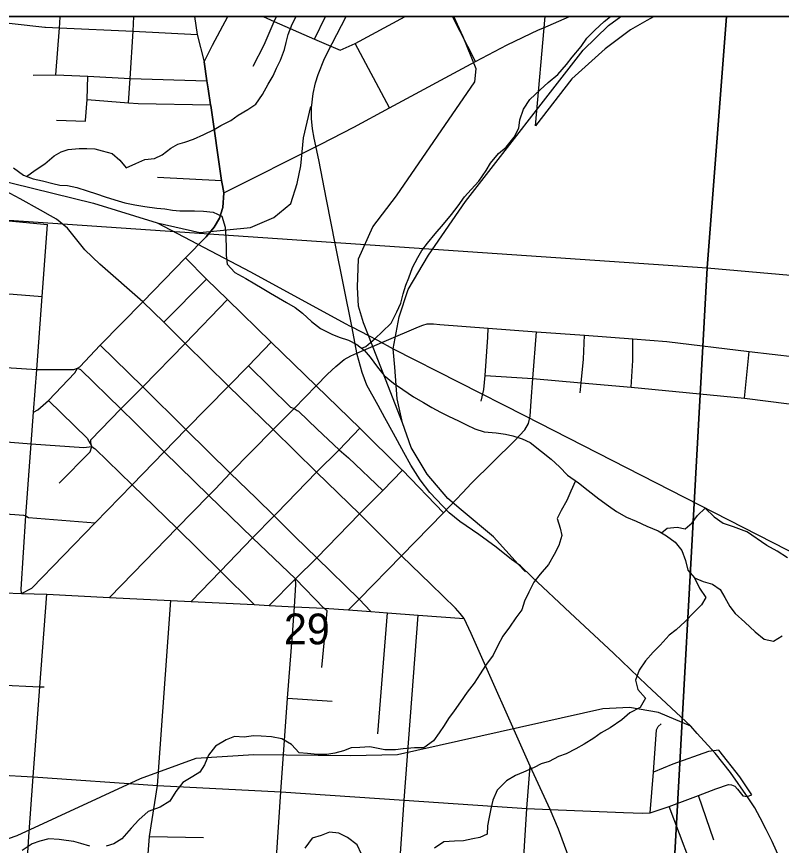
# Model space of a CAD drawing. Extents: x 0 to 42, y 0 to 22.
# Drawn here: x 2.931 to 3.451, y 20.336 to 20.9 of the extents above; entities that cross this region are included whole.
import ezdxf

# ---------------------------------------------------------------- set-up
doc = ezdxf.new("R2010")
doc.units = 0
for name, color, linetype in [('GM_X_City_Street', 7, 'Continuous'), ('GM_X_County_Road', 7, 'Continuous'), ('GM_X_Major_River', 7, 'Continuous'), ('GM_X_Minor_River', 7, 'Continuous'), ('GM_X_Rail_Line', 7, 'Continuous'), ('GM_X_Section', 7, 'Continuous'), ('GM_X_Section_Text', 7, 'Continuous'), ('GM_X_State_Route', 7, 'Continuous'), ('GM_X_Township_Road', 7, 'Continuous'), ('GM_X_Unincorporated', 7, 'Continuous'), ('SH_Cut_Line', 7, 'Continuous'), ('SH_Data', 7, 'Continuous')]:
    doc.layers.add(name, color=color, linetype=linetype)

msp = doc.modelspace()

# ---------------------------------------------------------------- linework, layer by layer
at = {"layer": 'GM_X_City_Street'}
for p, q in [((3.13371, 20.88467), (3.14117, 20.9)), ((3.24329, 20.8695), (3.22767, 20.9)), ((3.18471, 20.83794), (3.16148, 20.88163)), ((3.02687, 20.79076), (3.07048, 20.78857)), ((3.03111, 20.69207), (3.06023, 20.72129)), ((3.42632, 20.64032), (3.42946, 20.67221)), ((3.17687, 20.41197), (3.18328, 20.49428)), ((3.11541, 20.43617), (3.14566, 20.43425)), ((3.40557, 20.33954), (3.39508, 20.37005)), ((3.38911, 20.32526), (3.37516, 20.36249)), ((3.0215, 20.34215), (3.05817, 20.3414))]:
    msp.add_line(p, q, dxfattribs=at)
for points in [[(2.95757, 20.86044), (2.96009, 20.89239), (2.96034, 20.89552), (2.96069, 20.9)], [(3.00714, 20.8414), (3.00818, 20.85794), (3.01021, 20.88997), (3.01084, 20.9)], [(3.092, 20.86632), (3.09944, 20.88087), (3.10628, 20.89667), (3.10779, 20.9)], [(3.0987, 20.9), (3.10628, 20.89667), (3.13371, 20.88467), (3.15126, 20.87715)], [(3.15126, 20.87715), (3.16148, 20.88163), (3.19549, 20.9)], [(2.94219, 20.86006), (2.95757, 20.86044), (2.97944, 20.85935), (3.00818, 20.85794), (3.06047, 20.85628)], [(2.95814, 20.82944), (2.97788, 20.82886), (2.97792, 20.82935), (2.97902, 20.84354), (2.97944, 20.85935)], [(2.97902, 20.84354), (3.00714, 20.8414), (3.01363, 20.84091), (3.063, 20.83988)], [(3.01688, 20.70597), (2.98757, 20.73149), (2.97744, 20.74126), (2.96557, 20.75607), (2.95813, 20.76226), (2.95408, 20.76452), (2.9472, 20.76831), (2.93332, 20.7759), (2.92663, 20.77956), (2.9195, 20.78333), (2.91132, 20.78678), (2.90177, 20.78986), (2.89715, 20.79119), (2.89111, 20.7929), (2.8733, 20.79756), (2.85625, 20.80134)], [(2.81704, 20.76971), (2.85274, 20.76708), (2.88832, 20.76415), (2.92095, 20.76153), (2.95205, 20.75864)], [(2.93423, 20.50754), (2.9341, 20.5105), (2.93735, 20.56038), (2.94095, 20.60938), (2.94243, 20.63084), (2.94472, 20.65997), (2.9484, 20.70964), (2.95205, 20.75864)], [(2.83499, 20.71803), (2.84884, 20.71697), (2.85584, 20.71648), (2.88469, 20.71426), (2.91698, 20.71204), (2.9484, 20.70964)], [(2.95995, 20.58244), (2.98097, 20.60395), (2.98225, 20.60745), (2.98146, 20.61012), (2.98144, 20.61201), (3.00194, 20.63301), (3.01684, 20.64801), (3.0457, 20.67761), (3.07442, 20.70742)], [(3.24713, 20.63831), (3.24888, 20.64634), (3.2499, 20.6557), (3.25178, 20.68195), (3.25196, 20.68801)], [(3.3146, 20.64405), (3.31527, 20.65069), (3.31671, 20.66696), (3.31738, 20.68331)], [(3.34933, 20.64791), (3.3503, 20.666), (3.35034, 20.68066)], [(2.94243, 20.63084), (2.94549, 20.63247), (2.95265, 20.63883), (2.97066, 20.65752), (2.97231, 20.66069)], [(2.97231, 20.66069), (2.97448, 20.65993), (3.00194, 20.63301), (3.01156, 20.62369), (3.03141, 20.60393), (3.06189, 20.5741), (3.09149, 20.54532), (3.12072, 20.51736), (3.13995, 20.49752)], [(3.08877, 20.66235), (3.11739, 20.63424), (3.11982, 20.63325), (3.12192, 20.63198)], [(3.2499, 20.6557), (3.28241, 20.65376), (3.31527, 20.65069), (3.34933, 20.64791), (3.42632, 20.64032), (3.45677, 20.6366), (3.48794, 20.63254), (3.51876, 20.62922)], [(2.95265, 20.63883), (2.9789, 20.61313), (2.98225, 20.60745)], [(3.12192, 20.63198), (3.12275, 20.63147), (3.13554, 20.61929), (3.15055, 20.60518), (3.15694, 20.59987), (3.18027, 20.57751)], [(3.13512, 20.5901), (3.15055, 20.60518), (3.16445, 20.61986)], [(3.10295, 20.49931), (3.12072, 20.51736), (3.13522, 20.53183), (3.16438, 20.56158), (3.18027, 20.57751), (3.19354, 20.59136)], [(3.00954, 20.58149), (3.03994, 20.55188), (3.0697, 20.52264), (3.09259, 20.4999)], [(2.75236, 20.573), (2.80215, 20.5694), (2.8377, 20.5665), (2.87135, 20.56434), (2.87339, 20.56518), (2.89498, 20.56392), (2.90593, 20.56326), (2.9085, 20.56281), (2.93566, 20.56086), (2.93735, 20.56038)], [(2.93735, 20.56038), (2.93912, 20.55926), (2.98444, 20.55561)], [(3.04971, 20.50202), (3.0697, 20.52264), (3.09149, 20.54532), (3.10631, 20.56039)], [(3.17213, 20.49526), (3.16413, 20.5036), (3.13522, 20.53183), (3.12066, 20.54604), (3.10631, 20.56039)], [(3.15693, 20.49625), (3.16413, 20.5036), (3.19295, 20.53306)], [(3.1028, 20.21283), (3.10322, 20.22293), (3.10391, 20.26556), (3.10485, 20.28322), (3.11071, 20.37253), (3.11541, 20.43617), (3.1187, 20.47953), (3.12012, 20.49837), (3.12101, 20.51357), (3.12072, 20.51736)], [(3.01434, 20.25017), (3.0215, 20.34215), (3.02687, 20.37691), (3.03595, 20.50271)], [(3.13873, 20.45716), (3.14042, 20.47591), (3.14235, 20.49557), (3.13995, 20.49752)], [(3.1849, 20.20535), (3.18545, 20.21888), (3.18843, 20.2689), (3.18939, 20.28375), (3.19064, 20.30744), (3.19473, 20.36689), (3.20425, 20.4927)], [(2.88779, 20.44684), (2.91821, 20.44522), (2.94683, 20.44404), (2.94979, 20.44404)], [(3.36217, 20.35834), (3.36431, 20.38587), (3.36635, 20.41477), (3.36766, 20.41705), (3.36974, 20.41878)], [(3.40676, 20.37451), (3.41556, 20.37751), (3.41753, 20.37734), (3.41971, 20.37637), (3.42164, 20.37444), (3.4253, 20.36977), (3.42824, 20.36943), (3.43131, 20.37047), (3.42306, 20.38272), (3.40896, 20.40096), (3.40189, 20.39999), (3.37768, 20.39129), (3.36431, 20.38587)], [(3.26699, 20.20221), (3.26903, 20.21466), (3.27822, 20.36114), (3.28055, 20.38998)], [(2.95155, 20.21777), (2.93718, 20.25562), (2.93511, 20.26453), (2.93497, 20.27302), (2.93939, 20.34223), (2.94231, 20.38268)], [(3.2941, 20.36055), (3.34401, 20.35855), (3.35706, 20.35807), (3.36217, 20.35834), (3.37516, 20.36249), (3.39508, 20.37005), (3.40676, 20.37451)]]:
    msp.add_lwpolyline(points, dxfattribs=at)
at = {"layer": 'GM_X_County_Road'}
for p, q in [((3.07108, 20.78507), (3.07193, 20.78007)), ((3.108, 20.56214), (3.13512, 20.5901)), ((2.93423, 20.50754), (2.95149, 20.50699)), ((2.95149, 20.50699), (2.99425, 20.50479)), ((2.88228, 20.38637), (2.94231, 20.38268))]:
    msp.add_line(p, q, dxfattribs=at)
for points in [[(2.88531, 20.9), (2.95017, 20.89287), (2.95066, 20.89285)], [(3.05211, 20.9), (3.05391, 20.88785), (3.0586, 20.86918)], [(2.95066, 20.89285), (2.96009, 20.89239), (3.01021, 20.88997), (3.05391, 20.88785)], [(3.0586, 20.86918), (3.06047, 20.85628), (3.06132, 20.85081)], [(3.06132, 20.85081), (3.063, 20.83988), (3.06308, 20.83939)], [(3.06308, 20.83939), (3.07048, 20.78857), (3.07108, 20.78507)], [(3.07193, 20.78007), (3.07126, 20.77012), (3.06992, 20.7658)], [(3.06992, 20.7658), (3.06902, 20.76291), (3.06554, 20.7568), (3.05987, 20.75017), (3.04582, 20.73588)], [(3.04582, 20.73588), (3.06023, 20.72129), (3.07442, 20.70742), (3.10412, 20.67836), (3.13491, 20.6488)], [(2.97394, 20.66175), (2.98782, 20.67637), (3.01688, 20.70597)], [(3.13491, 20.6488), (3.14256, 20.65668), (3.14823, 20.66202), (3.15389, 20.66666), (3.15836, 20.66916), (3.16258, 20.67104), (3.20445, 20.68885), (3.20749, 20.69012), (3.21042, 20.69087), (3.21464, 20.6909), (3.21904, 20.69054), (3.25196, 20.68801), (3.28482, 20.68553), (3.31738, 20.68331), (3.35034, 20.68066), (3.37351, 20.67902), (3.42946, 20.67221), (3.46073, 20.66847), (3.49168, 20.66479), (3.52243, 20.66106), (3.55354, 20.65638)], [(3.28121, 20.63839), (3.28241, 20.65376), (3.28482, 20.68553)], [(2.98782, 20.67637), (3.01684, 20.64801), (3.0461, 20.61899)], [(3.07517, 20.64859), (3.08877, 20.66235), (3.10412, 20.67836)], [(2.84511, 20.66656), (2.88093, 20.66414), (2.89707, 20.66291), (2.9131, 20.66185), (2.94472, 20.65997)], [(2.94472, 20.65997), (2.96992, 20.65988), (2.97231, 20.66069), (2.97394, 20.66175)], [(2.93423, 20.50754), (2.94124, 20.51115), (2.98444, 20.55561), (3.00954, 20.58149), (3.03141, 20.60393), (3.0461, 20.61899), (3.07517, 20.64859)], [(3.10563, 20.61904), (3.11982, 20.63325), (3.13491, 20.6488)], [(3.13491, 20.6488), (3.16445, 20.61986), (3.19317, 20.59171)], [(3.23441, 20.57605), (3.24056, 20.58256), (3.26987, 20.61137), (3.27692, 20.61879), (3.27933, 20.62319), (3.28042, 20.62814), (3.28121, 20.63839)], [(3.0461, 20.61899), (3.07641, 20.58925), (3.094, 20.57228)], [(2.84168, 20.61663), (2.87706, 20.61406), (2.90947, 20.6117), (2.94095, 20.60938), (2.97678, 20.60686), (2.98225, 20.60745), (2.98396, 20.60622)], [(2.98396, 20.60622), (2.98439, 20.60591), (3.00954, 20.58149)], [(3.19317, 20.59171), (3.19354, 20.59136), (3.22145, 20.56236)], [(3.19295, 20.53306), (3.22145, 20.56236), (3.23441, 20.57605)], [(3.094, 20.57228), (3.10631, 20.56039), (3.108, 20.56214)], [(2.8337, 20.512), (2.86769, 20.51), (2.89118, 20.50914), (2.92266, 20.50788), (2.93423, 20.50754)], [(2.99425, 20.50479), (3.03595, 20.50271), (3.04971, 20.50202)], [(3.04971, 20.50202), (3.09259, 20.4999), (3.10295, 20.49931), (3.12012, 20.49837), (3.13995, 20.49752), (3.15693, 20.49625), (3.17213, 20.49526), (3.18328, 20.49428), (3.20425, 20.4927), (3.23548, 20.49043)], [(2.94231, 20.38268), (3.02687, 20.37691), (3.11071, 20.37253), (3.19473, 20.36689), (3.27822, 20.36114), (3.2941, 20.36055)]]:
    msp.add_lwpolyline(points, dxfattribs=at)
at = {"layer": 'GM_X_Major_River'}
for points in [[(2.92876, 20.79701), (2.93573, 20.79203), (2.94216, 20.78971), (2.94859, 20.78814), (2.95559, 20.78639), (2.9605, 20.7854), (2.96562, 20.78498), (2.97205, 20.78361), (2.97905, 20.78147), (2.98528, 20.77934), (2.99133, 20.7774), (2.99776, 20.77526), (3.00457, 20.77332), (3.01138, 20.77194), (3.01819, 20.77075), (3.02633, 20.76974), (3.03182, 20.76913), (3.03712, 20.76834), (3.04204, 20.76792), (3.05209, 20.76785), (3.05815, 20.76761), (3.06478, 20.76699), (3.07063, 20.76429), (3.07285, 20.75669), (3.07336, 20.74948), (3.0735, 20.74285), (3.07365, 20.73773), (3.07417, 20.73146), (3.07944, 20.72593), (3.08699, 20.7217), (3.09321, 20.71824), (3.09812, 20.71517), (3.10378, 20.7119), (3.10925, 20.70864), (3.11472, 20.70557), (3.12057, 20.70211), (3.12547, 20.69809), (3.13168, 20.69254), (3.13771, 20.68776), (3.14545, 20.68391), (3.15055, 20.68178), (3.15678, 20.67984), (3.16245, 20.67696), (3.16754, 20.67313), (3.17167, 20.66817), (3.17655, 20.66149), (3.18105, 20.65577), (3.18745, 20.6506), (3.19386, 20.64619), (3.20103, 20.64121), (3.20782, 20.63737), (3.21348, 20.63391), (3.21952, 20.63083), (3.225, 20.62814), (3.2316, 20.62505), (3.23708, 20.62217), (3.24293, 20.61947), (3.24917, 20.61753), (3.25731, 20.61671), (3.26375, 20.6159), (3.26867, 20.61473), (3.27509, 20.61259), (3.28038, 20.61009), (3.2881, 20.60415), (3.2947, 20.59879), (3.30034, 20.59363), (3.30599, 20.58809), (3.31334, 20.58272), (3.31993, 20.57756), (3.32728, 20.57181), (3.33388, 20.56721), (3.33915, 20.56319), (3.34594, 20.55935), (3.35256, 20.55664), (3.35992, 20.55317), (3.36767, 20.55008), (3.37332, 20.54663), (3.37917, 20.54241), (3.38367, 20.53669), (3.38609, 20.52984), (3.38774, 20.52338), (3.39225, 20.51804)], [(3.39225, 20.51804), (3.39811, 20.51553), (3.40454, 20.51377), (3.40981, 20.51013), (3.413, 20.5048), (3.41636, 20.49851), (3.41992, 20.49375), (3.42651, 20.48801)], [(3.42651, 20.48801), (3.43355, 20.48138), (3.43976, 20.4764), (3.446, 20.47502), (3.45191, 20.47877)]]:
    msp.add_lwpolyline(points, dxfattribs=at)
at = {"layer": 'GM_X_Minor_River'}
for points in [[(2.93781, 20.79128), (2.94367, 20.7954), (2.95013, 20.79991), (2.9566, 20.80536), (2.96135, 20.80798), (2.96609, 20.80966), (2.97366, 20.81018), (2.97877, 20.81014), (2.98426, 20.80992), (2.98916, 20.80856), (2.99596, 20.80681), (3.00123, 20.80241), (3.00555, 20.79708), (3.01219, 20.80006), (3.01826, 20.80268), (3.02489, 20.80339), (3.03001, 20.80582), (3.03591, 20.81052), (3.04066, 20.81314), (3.0454, 20.81463), (3.05128, 20.81667), (3.0583, 20.81966), (3.06532, 20.82322), (3.07007, 20.82584), (3.07672, 20.82921), (3.08185, 20.83296), (3.08831, 20.83671), (3.09382, 20.84046), (3.09841, 20.84688), (3.10224, 20.85406), (3.10549, 20.85972), (3.1078, 20.86501), (3.11048, 20.8703), (3.11337, 20.87749), (3.11454, 20.88241), (3.1159, 20.88771), (3.1186, 20.89489), (3.12133, 20.9)], [(3.16596, 20.67432), (3.16875, 20.67543), (3.17503, 20.68088), (3.17979, 20.68559), (3.18589, 20.69142), (3.18973, 20.69917), (3.19241, 20.70503), (3.19416, 20.71146), (3.1959, 20.71733), (3.19783, 20.72224), (3.20034, 20.72924), (3.20398, 20.73604), (3.20685, 20.74095), (3.21067, 20.74585), (3.21582, 20.75208), (3.22154, 20.75867), (3.22688, 20.76527), (3.23146, 20.77112), (3.23586, 20.77734), (3.24024, 20.78224), (3.24558, 20.78808), (3.25055, 20.79525), (3.25342, 20.80016), (3.25895, 20.80676), (3.26409, 20.81108), (3.26962, 20.81787), (3.27269, 20.82411), (3.27349, 20.82979), (3.276, 20.83697), (3.2802, 20.84358), (3.28725, 20.85017), (3.29277, 20.85525), (3.29924, 20.8607), (3.30515, 20.8673), (3.30897, 20.87239), (3.31526, 20.87955), (3.31909, 20.8854), (3.32442, 20.89067), (3.33089, 20.8967), (3.33519, 20.9)], [(3.3114, 20.58414), (3.30809, 20.57705), (3.3054, 20.57081), (3.30157, 20.56401), (3.29888, 20.55853), (3.30092, 20.55188), (3.30202, 20.54695), (3.30008, 20.54014), (3.29682, 20.5339), (3.29299, 20.5271), (3.28727, 20.52069), (3.28307, 20.51522), (3.27962, 20.50842), (3.27655, 20.50218), (3.27481, 20.49632), (3.2708, 20.49085), (3.2664, 20.48462), (3.26182, 20.47839), (3.25856, 20.47216), (3.2553, 20.46554), (3.25014, 20.45856), (3.24651, 20.4529), (3.2423, 20.44648), (3.23772, 20.44026), (3.23313, 20.43365), (3.22874, 20.42761), (3.22492, 20.42252), (3.22186, 20.41761), (3.21861, 20.4127), (3.21479, 20.40723), (3.20814, 20.40253), (3.2017, 20.40239), (3.19413, 20.40187), (3.18883, 20.40114), (3.18164, 20.40119), (3.17144, 20.40316), (3.16462, 20.40263), (3.15876, 20.40248), (3.15344, 20.40043), (3.14757, 20.39876), (3.14207, 20.39785), (3.13564, 20.3979), (3.12902, 20.39851), (3.12335, 20.39912), (3.11809, 20.40465), (3.1115, 20.40867), (3.1045, 20.40986), (3.09732, 20.41029), (3.09221, 20.41051), (3.08577, 20.40961), (3.07916, 20.41022), (3.07365, 20.40798), (3.06624, 20.40348), (3.06147, 20.39744), (3.05878, 20.39082), (3.05572, 20.38592), (3.05097, 20.38291), (3.04413, 20.37879), (3.03936, 20.37275), (3.03534, 20.36614), (3.02869, 20.36201), (3.02053, 20.35904), (3.01406, 20.35339), (3.00891, 20.34774), (3.00262, 20.34057), (2.99711, 20.3372), (2.99199, 20.33553)], [(3.36994, 20.54869), (3.37376, 20.55197), (3.38057, 20.55249), (3.38586, 20.55151), (3.39062, 20.55565), (3.39444, 20.56055), (3.39958, 20.56544), (3.40579, 20.55972), (3.41181, 20.55532), (3.4186, 20.55299), (3.42765, 20.54971)], [(3.4557, 20.53164), (3.44852, 20.53622), (3.44153, 20.54003), (3.42765, 20.54971)], [(3.39225, 20.51804), (3.3958, 20.51106), (3.40011, 20.50477), (3.39705, 20.49986), (3.39191, 20.49459), (3.386, 20.48837), (3.37991, 20.48272), (3.37515, 20.47915), (3.36905, 20.47237), (3.36429, 20.46766), (3.35895, 20.46163), (3.35456, 20.45521), (3.35224, 20.44859), (3.35371, 20.44214), (3.35897, 20.43622), (3.35533, 20.42999), (3.34831, 20.42624), (3.34279, 20.42154), (3.33499, 20.41609), (3.32873, 20.41272), (3.32378, 20.40896), (3.31713, 20.40484), (3.31162, 20.40184), (3.30498, 20.39828), (3.29986, 20.39661), (3.2934, 20.39324), (3.2879, 20.39157), (3.28316, 20.38914), (3.27595, 20.38596), (3.27044, 20.38353), (3.26436, 20.37997), (3.25808, 20.37357), (3.255, 20.36695), (3.25364, 20.36089), (3.25227, 20.35408), (3.25148, 20.34934), (3.25125, 20.34365), (3.24613, 20.34141), (3.24139, 20.3405), (3.23514, 20.33921), (3.22889, 20.33906), (3.2217, 20.33854), (3.21543, 20.33422)], [(3.16564, 20.33001), (3.16266, 20.33647), (3.15626, 20.34144), (3.15022, 20.34433), (3.14398, 20.34513), (3.13829, 20.34289), (3.13204, 20.34104), (3.12707, 20.33424)], [(2.98083, 20.3356), (2.97479, 20.33735), (2.96988, 20.33871), (2.96478, 20.3395), (2.95986, 20.3401), (2.95286, 20.34053), (2.9468, 20.33905), (2.94149, 20.33719), (2.93484, 20.33268)]]:
    msp.add_lwpolyline(points, dxfattribs=at)
at = {"layer": 'GM_X_Rail_Line'}
for p, q in [((3.15809, 20.68937), (3.15919, 20.6888)), ((3.15919, 20.6888), (3.17036, 20.683)), ((3.19363, 20.6236), (3.17036, 20.683)), ((3.27723, 20.52215), (3.2724, 20.52751))]:
    msp.add_line(p, q, dxfattribs=at)
for points in [[(2.43589, 20.9), (2.55679, 20.87545), (2.66669, 20.85076), (2.98339, 20.77295), (3.02658, 20.75958)], [(3.45027, 20.32762), (3.44525, 20.33873), (3.44113, 20.34687), (3.43694, 20.35477), (3.43332, 20.3616), (3.42888, 20.36851), (3.41682, 20.38569), (3.40638, 20.39885), (3.3942, 20.41228), (3.38976, 20.41719), (3.35988, 20.44513), (3.33716, 20.46677), (3.30771, 20.49433), (3.28154, 20.51869), (3.27396, 20.52618), (3.26785, 20.53066), (3.25743, 20.53901), (3.24546, 20.54771), (3.23255, 20.55649), (3.2254, 20.56243), (3.2121, 20.57609), (3.20568, 20.58473), (3.19931, 20.59489), (3.19457, 20.6035), (3.18743, 20.61642), (3.18157, 20.62701), (3.17703, 20.63547), (3.16942, 20.64924), (3.16623, 20.6578), (3.16281, 20.67002), (3.15916, 20.68926), (3.14801, 20.7444), (3.1418, 20.77557), (3.13657, 20.80245), (3.13339, 20.81718), (3.13229, 20.8237), (3.13177, 20.83065), (3.13177, 20.8379), (3.13287, 20.84772), (3.13428, 20.85482), (3.1361, 20.86067), (3.14059, 20.87142), (3.14582, 20.88171), (3.15524, 20.9)], [(3.17036, 20.683), (3.16699, 20.69161), (3.16375, 20.70292), (3.16295, 20.71585), (3.16375, 20.73524), (3.17345, 20.75705), (3.1896, 20.77806), (3.24291, 20.85562), (3.24371, 20.86451), (3.23483, 20.88632), (3.22864, 20.9)], [(3.18733, 20.67399), (3.19122, 20.69574), (3.19738, 20.71421), (3.21136, 20.73771), (3.23654, 20.77409), (3.31655, 20.87707), (3.33389, 20.89386), (3.34208, 20.9)], [(3.02658, 20.75958), (3.05573, 20.75301), (3.09006, 20.75644), (3.106, 20.76321), (3.11753, 20.77276), (3.12182, 20.78649), (3.1244, 20.79851), (3.12612, 20.8174), (3.13121, 20.83875)], [(3.02658, 20.75958), (3.09025, 20.72632), (3.15456, 20.69121), (3.15809, 20.68937)], [(3.17036, 20.683), (3.17656, 20.67977), (3.18733, 20.67399)], [(3.18733, 20.67399), (3.27662, 20.62849), (3.65369, 20.43582)], [(3.19363, 20.6236), (3.19004, 20.63996), (3.18841, 20.66152), (3.18733, 20.67399)], [(3.2724, 20.52751), (3.25564, 20.54612), (3.23352, 20.5644), (3.22434, 20.57215), (3.21038, 20.5887), (3.19961, 20.60674), (3.19363, 20.6236)], [(3.38976, 20.41719), (3.36772, 20.4265), (3.34799, 20.42979), (3.3299, 20.42896), (3.19016, 20.39773), (3.1581, 20.3969), (3.09234, 20.39773), (3.05288, 20.39526), (3.01507, 20.38129), (2.93122, 20.34265), (2.90738, 20.33443), (2.88272, 20.33196), (2.85642, 20.33525), (2.83258, 20.33772), (2.72572, 20.33279), (2.6953, 20.32539), (2.66817, 20.30566), (2.62461, 20.28264)]]:
    msp.add_lwpolyline(points, dxfattribs=at)
at = {"layer": 'GM_X_Section'}
for points in [[(2.88887, 20.76389), (3.40098, 20.72913), (3.37304, 20.22364), (2.8507, 20.2571)], [(3.90893, 20.68435), (3.86445, 20.18016), (3.37304, 20.22364), (3.40098, 20.72913)]]:
    msp.add_lwpolyline(points, close=True, dxfattribs=at)
at = {"layer": 'GM_X_State_Route'}
for p, q in [((3.28901, 20.89212), (3.30714, 20.9)), ((3.07193, 20.78007), (3.07108, 20.78507)), ((3.01688, 20.70597), (3.04582, 20.73588)), ((3.07517, 20.64859), (3.0457, 20.67761)), ((3.10563, 20.61904), (3.07517, 20.64859)), ((3.13512, 20.5901), (3.10563, 20.61904)), ((3.06189, 20.5741), (3.06625, 20.57864)), ((2.93423, 20.50754), (2.95149, 20.50699)), ((2.95149, 20.50699), (2.99425, 20.50479)), ((2.88228, 20.38637), (2.94231, 20.38268))]:
    msp.add_line(p, q, dxfattribs=at)
for points in [[(3.54361, 20.9), (3.36487, 20.9), (3.35986, 20.89744), (3.3487, 20.89096), (3.33142, 20.878), (3.30883, 20.85769), (3.28419, 20.8256), (3.29069, 20.9), (2.26236, 20.9)], [(3.0586, 20.86918), (3.06439, 20.88046), (3.07481, 20.9)], [(3.07193, 20.78007), (3.13802, 20.81313), (3.16038, 20.82483), (3.18471, 20.83794), (3.24329, 20.8695), (3.26475, 20.88086), (3.28626, 20.89093), (3.28901, 20.89212)], [(3.06132, 20.85081), (3.06047, 20.85628), (3.0586, 20.86918)], [(3.06308, 20.83939), (3.063, 20.83988), (3.06132, 20.85081)], [(3.07108, 20.78507), (3.07048, 20.78857), (3.06308, 20.83939)], [(3.06992, 20.7658), (3.07126, 20.77012), (3.07193, 20.78007)], [(3.04582, 20.73588), (3.05987, 20.75017), (3.06554, 20.7568), (3.06902, 20.76291), (3.06992, 20.7658)], [(3.0457, 20.67761), (3.03111, 20.69207), (3.01688, 20.70597)], [(3.06625, 20.57864), (3.07641, 20.58925), (3.10563, 20.61904)], [(3.23548, 20.49043), (3.23282, 20.49388), (3.22961, 20.49739), (3.21298, 20.51387), (3.19295, 20.53306), (3.16438, 20.56158), (3.13512, 20.5901)], [(2.99425, 20.50479), (3.01833, 20.52936), (3.03994, 20.55188), (3.06189, 20.5741)], [(2.8337, 20.512), (2.86769, 20.51), (2.89118, 20.50914), (2.92266, 20.50788), (2.93423, 20.50754)], [(2.94231, 20.38268), (2.94683, 20.44404), (2.95149, 20.50699)], [(3.33523, 20.23565), (3.32776, 20.26537), (3.31768, 20.2983), (3.29982, 20.34714), (3.2941, 20.36055), (3.28055, 20.38998), (3.24027, 20.48026), (3.23548, 20.49043)]]:
    msp.add_lwpolyline(points, dxfattribs=at)
at = {"layer": 'GM_X_Township_Road'}
msp.add_lwpolyline([(5.44663, 20.9), (2.33491, 20.9), (2.32756, 20.8303), (2.32532, 20.80909), (2.30663, 20.5555), (2.29028, 20.33374), (2.26737, 20.02303)], dxfattribs=at)
at = {"layer": 'GM_X_Unincorporated'}
for points in [[(3.41399, 20.9), (2.90183, 20.9), (2.88887, 20.76389), (3.40098, 20.72913)], [(3.9262, 20.9), (3.41399, 20.9), (3.40098, 20.72913), (3.90893, 20.68435)]]:
    msp.add_lwpolyline(points, close=True, dxfattribs=at)
at = {"layer": 'SH_Cut_Line'}
msp.add_lwpolyline([(8.604, 20.9), (2.1, 20.9), (2.1, 14.1)], dxfattribs=at)
at = {"layer": 'SH_Data'}
msp.add_line((2.1, 20.9), (8.9, 20.9), dxfattribs=at)

# ---------------------------------------------------------------- texts
at = {"layer": 'GM_X_Section_Text'}
msp.add_text('29', height=0.020928, rotation=0, dxfattribs=at).set_placement((3.11293, 20.47288))

doc.saveas('drawing.dxf')
